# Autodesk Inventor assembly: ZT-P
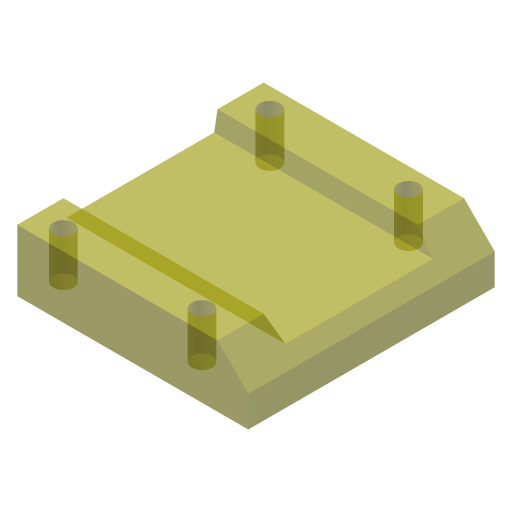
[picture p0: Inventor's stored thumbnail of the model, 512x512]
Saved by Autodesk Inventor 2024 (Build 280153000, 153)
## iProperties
Company: ATC
Created: 2023-03
Part Number: ZT-P
Document SubType Name: Assembly
Designer: Andrzej Jaskulski
Manufacturer: Standard
Standards Organization: Custom
Checked By: A.J.
Engr Approved By: Andrzej Jaskulski
Mfg Approved By: Andrzej Jaskulski
Authority: A.J.
Title: A.J.: Kurs R2024-MEP
Author: Andrzej Jaskulski
Revision Number: 1/24
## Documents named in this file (2)
- C:\Users\AndJas\Documents\R2024-MEP\Obszar roboczy\ZT-P.iam
- C:\Users\AndJas\Documents\R2024-MEP\Obszar roboczy\ZT-Dół.ipt
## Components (1 placed, 1 different names)
1. ZT-Dół:1
